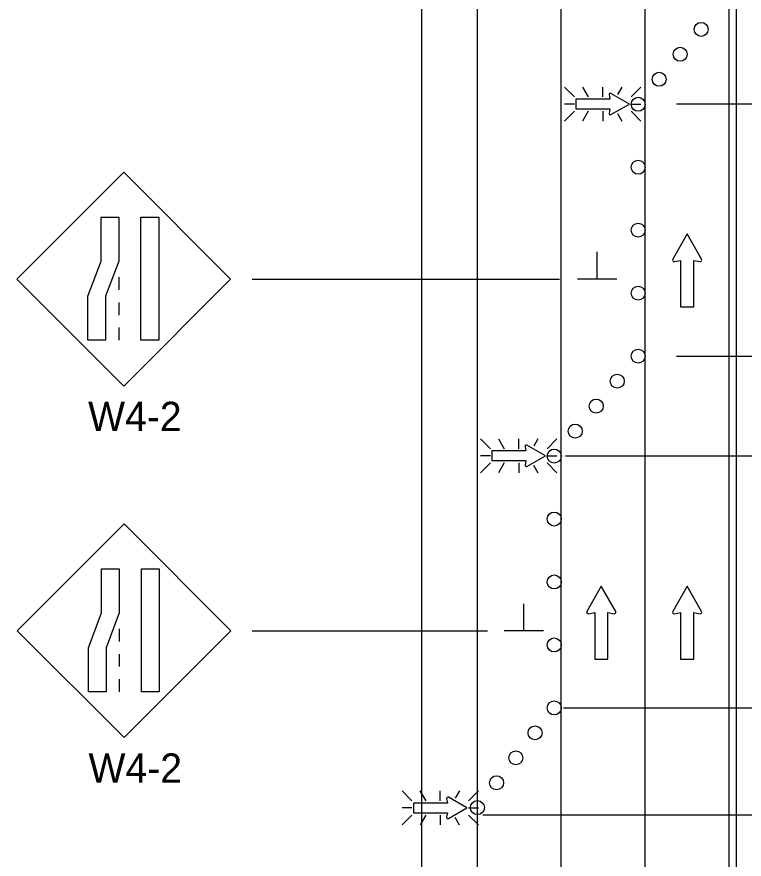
# Model space of a CAD drawing. Extents: x 16473 to 18475, y 7005 to 8296.
# Drawn here: x 16798.5 to 17006.4, y 7717.6 to 7958.4 of the extents above; entities that cross this region are included whole.
import ezdxf

# ---------------------------------------------------------------- set-up
doc = ezdxf.new("R2010")
doc.units = 0
for name, color, linetype in [('ALI_LEGAL_EX', 7, 'Continuous'), ('MT_SCRATCH_LEVEL_E', 7, 'Continuous'), ('PAVT_EDGE_EX', 7, 'Continuous'), ('TRAFFIC_SIGNS_PR', 7, 'Continuous'), ('TYPICAL_TEXT_DIMEN_PR', 7, 'Continuous')]:
    doc.layers.add(name, color=color, linetype=linetype)

msp = doc.modelspace()

# ---------------------------------------------------------------- linework, layer by layer
at = {"layer": 'ALI_LEGAL_EX'}
for p, q in [((16954.13, 7361.76), (16954.13, 8295.71)), ((16978.13, 7361.76), (16978.13, 8295.71)), ((17002.13, 7361.76), (17002.13, 8295.71)), ((17004.11, 8234.45), (17004.11, 7405.27))]:
    msp.add_line(p, q, dxfattribs=at)
for points in [[(16954.13, 7861.76), (16954.13, 7886.76)], [(17002.13, 7861.76), (17002.13, 7886.76)], [(16978.13, 7761.76), (16978.13, 7786.76)], [(17002.13, 7761.76), (17002.13, 7786.76)]]:
    msp.add_lwpolyline(points, dxfattribs=at)
at = {"layer": 'MT_SCRATCH_LEVEL_E'}
for p, q in [((16990.1, 7896.31), (16985.98, 7889.07)), ((16994.24, 7889.07), (16990.1, 7896.31)), ((16986.47, 7888.39), (16988.24, 7888.7)), ((16988.24, 7888.7), (16988.24, 7875.45)), ((16991.99, 7875.45), (16991.99, 7888.7)), ((16991.99, 7888.7), (16993.76, 7888.39)), ((16988.24, 7875.45), (16991.99, 7875.45)), ((16965.57, 7795.67), (16961.46, 7788.43)), ((16969.71, 7788.43), (16965.57, 7795.67)), ((16990.1, 7795.67), (16985.98, 7788.43)), ((16994.24, 7788.43), (16990.1, 7795.67)), ((16961.94, 7787.74), (16963.71, 7788.06)), ((16963.71, 7788.06), (16963.71, 7774.8)), ((16967.46, 7774.8), (16967.46, 7788.06)), ((16967.46, 7788.06), (16969.23, 7787.74)), ((16986.47, 7787.74), (16988.24, 7788.06)), ((16988.24, 7788.06), (16988.24, 7774.8)), ((16991.99, 7774.8), (16991.99, 7788.06)), ((16991.99, 7788.06), (16993.76, 7787.74)), ((16963.71, 7774.8), (16967.46, 7774.8)), ((16988.24, 7774.8), (16991.99, 7774.8))]:
    msp.add_line(p, q, dxfattribs=at)
for centre, start, end in [((16986.39, 7888.85), 150.4248, 279.9638), ((16993.83, 7888.85), 260.0362, 29.7731), ((16961.86, 7788.2), 150.4248, 279.9638), ((16969.3, 7788.2), 260.0362, 29.7731), ((16986.39, 7788.2), 150.4248, 279.9638), ((16993.83, 7788.2), 260.0362, 29.7731)]:
    msp.add_arc(centre, 0.463, start, end, dxfattribs=at)
at = {"layer": 'PAVT_EDGE_EX'}
for p, q in [((16914.13, 8215.4), (16914.13, 7361.76)), ((16930.13, 8215.4), (16930.13, 7361.76))]:
    msp.add_line(p, q, dxfattribs=at)
at = {"layer": 'TRAFFIC_SIGNS_PR'}
for p, q in [((16957.9, 7935.49), (16955.08, 7938.31)), ((16960.2, 7938.31), (16961.83, 7935.49)), ((16965.99, 7935.49), (16965.99, 7938.31)), ((16971.46, 7938.31), (16970.25, 7936.21)), ((16976.89, 7938.3), (16974.07, 7935.49)), ((16957.9, 7933.45), (16955.08, 7933.45)), ((16974.07, 7933.45), (16976.89, 7933.45)), ((16957.9, 7931.42), (16955.08, 7928.6)), ((16961.85, 7931.42), (16960.22, 7928.6)), ((16965.99, 7931.42), (16965.99, 7928.6)), ((16970.17, 7930.79), (16971.43, 7928.6)), ((16976.89, 7928.6), (16974.07, 7931.42)), ((16829.02, 7913.93), (16798.47, 7883.38)), ((16859.56, 7883.38), (16829.02, 7913.93)), ((16798.47, 7883.38), (16829.02, 7852.84)), ((16827.61, 7883.94), (16827.61, 7880.34)), ((16829.02, 7852.84), (16859.56, 7883.38)), ((16827.61, 7876.74), (16827.61, 7873.14)), ((16827.61, 7869.54), (16827.61, 7865.94)), ((16933.9, 7834.92), (16931.08, 7837.74)), ((16936.2, 7837.74), (16937.83, 7834.92)), ((16941.99, 7834.92), (16941.99, 7837.74)), ((16947.46, 7837.74), (16946.25, 7835.65)), ((16952.89, 7837.74), (16950.07, 7834.92)), ((16933.9, 7832.89), (16931.08, 7832.89)), ((16950.07, 7832.89), (16952.89, 7832.89)), ((16933.9, 7830.86), (16931.08, 7828.04)), ((16937.85, 7830.86), (16936.22, 7828.04)), ((16941.99, 7830.86), (16941.99, 7828.04)), ((16952.89, 7828.04), (16950.07, 7830.86)), ((16946.17, 7830.22), (16947.43, 7828.04)), ((16829.13, 7813.42), (16798.59, 7782.87)), ((16859.68, 7782.87), (16829.13, 7813.42)), ((16798.59, 7782.87), (16829.13, 7752.32)), ((16827.73, 7783.42), (16827.73, 7779.82)), ((16829.13, 7752.32), (16859.68, 7782.87)), ((16827.73, 7776.22), (16827.73, 7772.62)), ((16827.73, 7769.02), (16827.73, 7765.42)), ((16911.44, 7734.26), (16908.62, 7737.08)), ((16913.73, 7737.08), (16915.36, 7734.26)), ((16919.52, 7734.26), (16919.52, 7737.08)), ((16924.99, 7737.08), (16923.78, 7734.99)), ((16930.42, 7737.08), (16927.61, 7734.26)), ((16911.44, 7732.23), (16908.62, 7732.23)), ((16927.61, 7732.23), (16930.42, 7732.23)), ((16911.44, 7730.19), (16908.62, 7727.37)), ((16915.39, 7730.19), (16913.76, 7727.37)), ((16919.52, 7730.19), (16919.52, 7727.37)), ((16923.7, 7729.56), (16924.97, 7727.37)), ((16930.42, 7727.38), (16927.61, 7730.19))]:
    msp.add_line(p, q, dxfattribs=at)
for points in [[(16968.31, 7930.44), (16973.62, 7933.45), (16968.31, 7936.49)], [(16967.81, 7936.14), (16968.04, 7934.84), (16958.32, 7934.84), (16958.32, 7932.1), (16968.04, 7932.1), (16967.81, 7930.79)], [(16943.81, 7835.57), (16944.04, 7834.28), (16934.32, 7834.28), (16934.32, 7831.53), (16944.04, 7831.53), (16943.81, 7830.23)], [(16944.31, 7829.88), (16949.62, 7832.89), (16944.31, 7835.93)], [(16921.35, 7734.91), (16921.58, 7733.61), (16911.85, 7733.61), (16911.85, 7730.87), (16921.58, 7730.87), (16921.35, 7729.57)], [(16921.85, 7729.21), (16927.16, 7732.23), (16921.85, 7735.27)]]:
    msp.add_lwpolyline(points, dxfattribs=at)
for points in [[(16827.61, 7901.09), (16827.61, 7888.51), (16823.85, 7878.52), (16823.85, 7865.94), (16818.79, 7865.94), (16818.79, 7878.52), (16822.56, 7888.51), (16822.56, 7901.09)], [(16839.02, 7901.09), (16839.02, 7865.94), (16833.96, 7865.94), (16833.96, 7901.09)], [(16827.73, 7800.57), (16827.73, 7787.99), (16823.97, 7778), (16823.97, 7765.42), (16818.91, 7765.42), (16818.91, 7778), (16822.67, 7787.99), (16822.67, 7800.57)], [(16839.13, 7800.57), (16839.13, 7765.42), (16834.08, 7765.42), (16834.08, 7800.57)]]:
    msp.add_lwpolyline(points, close=True, dxfattribs=at)
for centre in [(16994.13, 7954.8), (16988.13, 7947.66), (16982.13, 7940.52), (16976.13, 7933.38), (16976.13, 7915.38), (16976.13, 7897.38), (16976.13, 7879.38), (16976.13, 7861.38), (16970.13, 7854.24), (16964.13, 7847.1), (16958.13, 7839.96), (16952.13, 7832.82), (16952.13, 7814.82), (16952.13, 7796.82), (16952.13, 7778.82), (16952.13, 7760.82), (16946.63, 7753.69), (16941.13, 7746.56), (16935.64, 7739.43), (16930.14, 7732.31)]:
    msp.add_circle(centre, 2, dxfattribs=at)
for centre, start, end in [((16968.15, 7936.19), 61.4833, 189.9593), ((16968.15, 7930.74), 170.7308, 298.8916), ((16944.15, 7835.63), 61.4833, 189.9593), ((16944.15, 7830.17), 170.7308, 298.8916), ((16921.68, 7734.97), 61.4833, 189.9593), ((16921.68, 7729.51), 170.7308, 298.8916)]:
    msp.add_arc(centre, 0.341, start, end, dxfattribs=at)
at = {"layer": 'TYPICAL_TEXT_DIMEN_PR'}
for p, q in [((17118.17, 7933.38), (16987.03, 7933.38)), ((16964.44, 7883.38), (16964.44, 7891.17)), ((16865.77, 7883.38), (16953.59, 7883.38)), ((16970.06, 7883.38), (16958.81, 7883.38)), ((16987.03, 7861.38), (17118.17, 7861.38)), ((17118.17, 7832.82), (16955.35, 7832.82)), ((16943.44, 7782.82), (16943.44, 7790.61)), ((16865.77, 7782.82), (16933.06, 7782.82)), ((16949.07, 7782.82), (16937.82, 7782.82)), ((16954.73, 7760.82), (17118.17, 7760.82)), ((16931.74, 7730.26), (17091.13, 7730.26))]:
    msp.add_line(p, q, dxfattribs=at)

# ---------------------------------------------------------------- texts
at = {"layer": 'TRAFFIC_SIGNS_PR'}
for p in [(16818.84, 7839.97), (16818.96, 7739.45)]:
    msp.add_text('W4-2', height=8.37, dxfattribs=at).set_placement(p)

doc.saveas('drawing.dxf')
